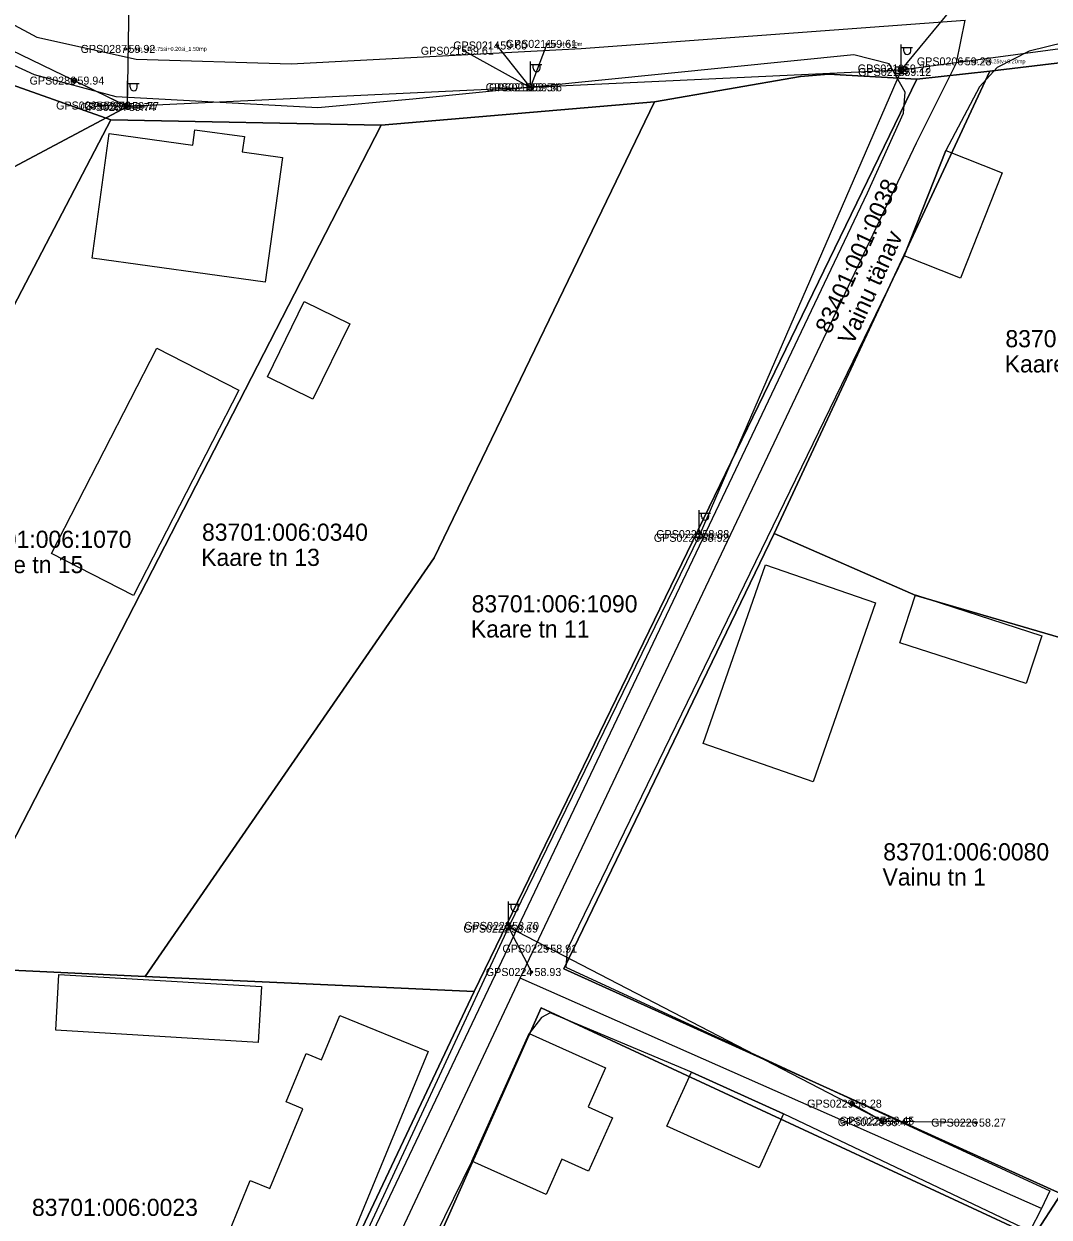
# Model space of a CAD drawing. Extents: x 580119 to 583377, y 6518915 to 6520820.
# Drawn here: x 581623.1 to 581712.7, y 6519628.5 to 6519732.9 of the extents above; entities that cross this region are included whole.
import ezdxf

# ---------------------------------------------------------------- set-up
doc = ezdxf.new("R2010")
doc.units = 0
for name, color, linetype in [('Hoone Elu- või ühiskondlik hoone', 7, 'Continuous'), ('Hoone Kõrval- või tootmishoone', 7, 'Continuous'), ('L_AADRESS', 7, 'Continuous'), ('MAAMUDEL', 7, 'Continuous'), ('MOOTKORG-EH2000', 7, 'Continuous'), ('MOOTMPUNKT', 7, 'Continuous'), ('MOOTNR', 7, 'Continuous'), ('MPOHULIIN', 7, 'Continuous'), ('PIIR', 7, 'Continuous'), ('POST', 7, 'Continuous'), ('Rippe kõrgus', 7, 'Continuous'), ('SIOHULIIN', 7, 'Continuous'), ('SIRAJATIS', 7, 'Continuous'), ('Tee Liiklusala', 7, 'Continuous'), ('Tee Tänav Pinnas', 7, 'Continuous'), ('Tee Tänav Püsikate', 7, 'Continuous'), ('TUNNUS', 7, 'Continuous')]:
    doc.layers.add(name, color=color, linetype=linetype)

msp = doc.modelspace()

# ---------------------------------------------------------------- linework, layer by layer
at = {"layer": 'Hoone Elu- või ühiskondlik hoone'}
for points in [[(581629.07, 6519712.38), (581630.57, 6519723.28), (581637.86, 6519722.27), (581638.05, 6519723.6), (581642.37, 6519723.01), (581642.19, 6519721.68), (581645.7, 6519721.2), (581644.2, 6519710.29)], [(581697.53, 6519682.25), (581692.1, 6519666.59), (581682.48, 6519669.93), (581687.92, 6519685.58)], [(581658.44, 6519643), (581648.72, 6519619.39), (581641.45, 6519622.37), (581643.12, 6519626.43), (581641.06, 6519627.29), (581642.88, 6519631.72), (581644.61, 6519631.02), (581647.48, 6519638), (581646.03, 6519638.6), (581647.78, 6519642.84), (581649.12, 6519642.29), (581650.72, 6519646.17)], [(581674.54, 6519637.2), (581672.46, 6519632.55), (581670.13, 6519633.6), (581668.74, 6519630.5), (581662.25, 6519633.41), (581667.25, 6519644.57), (581673.94, 6519641.58), (581672.41, 6519638.16)]]:
    msp.add_lwpolyline(points, close=True, dxfattribs=at)
at = {"layer": 'Hoone Kõrval- või tootmishoone'}
for points in [[(581700.04, 6519712.59), (581703.68, 6519721.79), (581708.61, 6519719.84), (581704.97, 6519710.64)], [(581644.4, 6519702), (581647.61, 6519708.59), (581651.59, 6519706.65), (581648.37, 6519700.06)], [(581625.51, 6519686.56), (581634.71, 6519704.51), (581641.88, 6519700.84), (581632.67, 6519682.88)], [(581712.06, 6519679.37), (581710.7, 6519675.18), (581699.67, 6519678.75), (581701.03, 6519682.95)], [(581643.87, 6519648.68), (581643.58, 6519643.81), (581625.88, 6519644.86), (581626.16, 6519649.75)], [(581689.5, 6519637.55), (581687.36, 6519632.83), (581679.31, 6519636.47), (581681.44, 6519641.2)]]:
    msp.add_lwpolyline(points, close=True, dxfattribs=at)
at = {"layer": 'MOOTMPUNKT'}
for centre in [(581631.98, 6519730.68), (581661.57, 6519730.52), (581664.48, 6519730.98), (581668.85, 6519731.12), (581705.07, 6519729.59), (581699.76, 6519728.97), (581699.8, 6519728.66), (581627.52, 6519727.91), (581667.24, 6519727.33), (581667.53, 6519727.32), (581629.84, 6519725.73), (581632.02, 6519725.6), (581632.31, 6519725.69), (581682.08, 6519687.93), (581682.15, 6519688.25), (581665.43, 6519653.76), (581665.52, 6519653.99), (581668.85, 6519652), (581667.47, 6519649.96), (581695.48, 6519638.45), (581698.16, 6519636.83), (581698.32, 6519636.96), (581706.32, 6519636.79)]:
    msp.add_circle(centre, 0.1, dxfattribs=at)
at = {"layer": 'MPOHULIIN'}
for p, q in [((581667.38, 6519727.32), (581668.85, 6519731.12)), ((581632.17, 6519725.65), (581629.84, 6519725.73)), ((581665.47, 6519653.88), (581667.47, 6519649.96))]:
    msp.add_line(p, q, dxfattribs=at)
for points in [[(581735.41, 6519733.61), (581699.78, 6519728.81), (581667.38, 6519727.32), (581632.17, 6519725.65), (581588.51, 6519746.8), (581548.1, 6519772.1), (581506.27, 6519795.87), (581500.22, 6519788.21)], [(581699.78, 6519728.81), (581708.5, 6519739.39), (581711.66, 6519739.66)], [(581699.78, 6519728.81), (581682.12, 6519688.09), (581665.47, 6519653.88), (581651.78, 6519624.49)], [(581632.17, 6519725.65), (581597.69, 6519707.32), (581584.75, 6519682.99), (581566.56, 6519648.72), (581550.4, 6519618.5), (581533.47, 6519586.34), (581516.09, 6519553.13), (581497.65, 6519517.94), (581481.23, 6519486.69), (581467.73, 6519460.68), (581429.35, 6519419.09), (581418, 6519374.32)], [(581706.32, 6519636.79), (581698.24, 6519636.9), (581665.47, 6519653.88)]]:
    msp.add_lwpolyline(points, dxfattribs=at)
at = {"layer": 'PIIR'}
for points in [[(581739.49, 6519732.55), (581707.53, 6519728.73), (581701.15, 6519728.05), (581693.43, 6519728.46), (581690.97, 6519728.27), (581678.23, 6519726.06), (581654.32, 6519724.01), (581630.7, 6519724.48), (581611.94, 6519731.13), (581605.95, 6519734.79), (581570.73, 6519755.43), (581571.67, 6519757.17), (581537.79, 6519776.58), (581472.84, 6519812.4), (581454.3, 6519820.58), (581425.45, 6519836.48)], [(581642.61, 6519606.31), (581662.45, 6519648.25), (581701.15, 6519728.05), (581707.53, 6519728.73), (581688.69, 6519688.3), (581670.29, 6519650.23), (581713.76, 6519630.56), (581711.33, 6519626.84), (581668.3, 6519646.83), (581659, 6519625.86)]]:
    msp.add_lwpolyline(points, dxfattribs=at)
for points in [[(581688.69, 6519688.3), (581707.53, 6519728.73), (581739.49, 6519732.55), (581716.34, 6519678.43), (581701.05, 6519682.87)], [(581570.76, 6519656.3), (581607.19, 6519725.15), (581611.94, 6519731.13), (581630.7, 6519724.48), (581592.07, 6519650.42)], [(581658.95, 6519686.18), (581678.23, 6519726.06), (581690.97, 6519728.27), (581693.43, 6519728.46), (581701.15, 6519728.05), (581662.45, 6519648.25), (581633.71, 6519649.56)], [(581616.49, 6519650.37), (581654.32, 6519724.01), (581678.23, 6519726.06), (581658.95, 6519686.18), (581633.71, 6519649.56)], [(581592.07, 6519650.42), (581630.7, 6519724.48), (581654.32, 6519724.01), (581616.49, 6519650.37)], [(581688.69, 6519688.3), (581701.05, 6519682.87), (581716.34, 6519678.43), (581738.8, 6519670.79), (581724.56, 6519646.71), (581713.76, 6519630.56), (581670.29, 6519650.23)], [(581616.49, 6519650.37), (581633.71, 6519649.56), (581662.45, 6519648.25), (581642.61, 6519606.31), (581598.4, 6519615.73)], [(581668.3, 6519646.83), (581711.33, 6519626.84), (581739.28, 6519615.28), (581729.24, 6519593.6), (581659, 6519625.86)], [(581713.76, 6519630.56), (581724.56, 6519646.71), (581749.03, 6519634.03), (581741.24, 6519619.07), (581739.28, 6519615.28), (581711.33, 6519626.84)]]:
    msp.add_lwpolyline(points, close=True, dxfattribs=at)
at = {"layer": 'POST'}
for p, q in [((581699.78, 6519729.06), (581699.78, 6519731.06)), ((581699.78, 6519730.81), (581700.78, 6519730.81)), ((581700.01, 6519730.49), (581700.01, 6519730.81)), ((581700.62, 6519730.49), (581700.62, 6519730.81)), ((581667.38, 6519727.57), (581667.38, 6519729.57)), ((581667.38, 6519729.32), (581668.38, 6519729.32)), ((581667.61, 6519729), (581667.61, 6519729.32)), ((581668.22, 6519729), (581668.22, 6519729.32)), ((581699.78, 6519728.81), (581699.78, 6519728.81)), ((581632.17, 6519725.9), (581632.17, 6519727.9)), ((581632.17, 6519727.65), (581633.17, 6519727.65)), ((581632.39, 6519727.33), (581632.39, 6519727.65)), ((581633.01, 6519727.33), (581633.01, 6519727.65)), ((581667.38, 6519727.32), (581667.38, 6519727.32)), ((581632.17, 6519725.65), (581632.17, 6519725.65)), ((581682.12, 6519688.34), (581682.12, 6519690.34)), ((581682.12, 6519690.09), (581683.12, 6519690.09)), ((581682.34, 6519689.77), (581682.34, 6519690.09)), ((581682.96, 6519689.77), (581682.96, 6519690.09)), ((581682.12, 6519688.09), (581682.12, 6519688.09)), ((581665.47, 6519654.13), (581665.47, 6519656.13)), ((581665.47, 6519655.88), (581666.47, 6519655.88)), ((581665.7, 6519655.55), (581665.7, 6519655.88)), ((581666.31, 6519655.55), (581666.31, 6519655.88)), ((581665.47, 6519653.88), (581665.47, 6519653.88))]:
    msp.add_line(p, q, dxfattribs=at)
for points in [[(581627.52, 6519727.91), (581632.17, 6519725.65)], [(581695.48, 6519638.45), (581698.24, 6519636.9)]]:
    msp.add_lwpolyline(points, dxfattribs=at)
for centre, radius in [((581699.78, 6519728.81), 0.25), ((581627.52, 6519727.91), 0.2), ((581667.38, 6519727.32), 0.25), ((581632.17, 6519725.65), 0.25), ((581682.12, 6519688.09), 0.25), ((581665.47, 6519653.88), 0.25), ((581695.48, 6519638.45), 0.2), ((581698.24, 6519636.9), 0.25)]:
    msp.add_circle(centre, radius, dxfattribs=at)
for centre in [(581700.31, 6519730.49), (581667.92, 6519729), (581632.7, 6519727.33), (581682.65, 6519689.77), (581666.01, 6519655.55)]:
    msp.add_arc(centre, 0.306, 180, 0, dxfattribs=at)
at = {"layer": 'SIOHULIIN'}
msp.add_line((581661.57, 6519730.52), (581667.38, 6519727.32), dxfattribs=at)
for points in [[(581632.17, 6519725.65), (581588.51, 6519746.8), (581548.1, 6519772.1), (581506.27, 6519795.87)], [(581667.38, 6519727.32), (581632.17, 6519725.65), (581632.41, 6519742.48)], [(581699.78, 6519728.81), (581667.38, 6519727.32), (581664.48, 6519730.98)], [(581429.35, 6519419.09), (581467.73, 6519460.68), (581481.23, 6519486.69), (581497.65, 6519517.94), (581516.09, 6519553.13), (581533.47, 6519586.34), (581550.4, 6519618.5), (581566.56, 6519648.72), (581584.75, 6519682.99), (581597.69, 6519707.32), (581632.17, 6519725.65)]]:
    msp.add_lwpolyline(points, dxfattribs=at)
at = {"layer": 'SIRAJATIS'}
msp.add_lwpolyline([(581699.28, 6519729.11), (581700.28, 6519729.11), (581700.28, 6519728.51), (581699.28, 6519728.51)], close=True, dxfattribs=at)
for centre, radius in [((581699.58, 6519728.81), 0.0304), ((581699.58, 6519728.81), 0.029), ((581699.58, 6519728.81), 0.0277), ((581699.58, 6519728.81), 0.0263), ((581699.58, 6519728.81), 0.0249), ((581699.58, 6519728.81), 0.0236), ((581699.58, 6519728.81), 0.0222), ((581699.58, 6519728.81), 0.0209), ((581699.58, 6519728.81), 0.0195), ((581699.58, 6519728.81), 0.0181), ((581699.58, 6519728.81), 0.0168), ((581699.58, 6519728.81), 0.0154), ((581699.58, 6519728.81), 0.014), ((581699.58, 6519728.81), 0.0127), ((581699.58, 6519728.81), 0.0113), ((581699.58, 6519728.81), 0.00996), ((581699.58, 6519728.81), 0.0086), ((581699.58, 6519728.81), 0.00724), ((581699.58, 6519728.81), 0.00587), ((581699.58, 6519728.81), 0.00451), ((581699.58, 6519728.81), 0.00315), ((581699.58, 6519728.81), 0.00179), ((581699.58, 6519728.81), 0.000426), ((581699.98, 6519728.81), 0.0304), ((581699.98, 6519728.81), 0.029), ((581699.98, 6519728.81), 0.0277), ((581699.98, 6519728.81), 0.0263), ((581699.98, 6519728.81), 0.0249), ((581699.98, 6519728.81), 0.0236), ((581699.98, 6519728.81), 0.0222), ((581699.98, 6519728.81), 0.0209), ((581699.98, 6519728.81), 0.0195), ((581699.98, 6519728.81), 0.0181), ((581699.98, 6519728.81), 0.0168), ((581699.98, 6519728.81), 0.0154), ((581699.98, 6519728.81), 0.014), ((581699.98, 6519728.81), 0.0127), ((581699.98, 6519728.81), 0.0113), ((581699.98, 6519728.81), 0.00996), ((581699.98, 6519728.81), 0.0086), ((581699.98, 6519728.81), 0.00724), ((581699.98, 6519728.81), 0.00587), ((581699.98, 6519728.81), 0.00451), ((581699.98, 6519728.81), 0.00315), ((581699.98, 6519728.81), 0.00179), ((581699.98, 6519728.81), 0.000426)]:
    msp.add_circle(centre, radius, dxfattribs=at)
at = {"layer": 'Tee Liiklusala'}
for points in [[(581644.12, 6519607.31), (581696.84, 6519718.1), (581699.98, 6519725.05), (581700.13, 6519726.91), (581698.74, 6519729.38), (581695.65, 6519730.16), (581657.1, 6519726.3), (581648.78, 6519725.52), (581631.18, 6519726.49), (581624.02, 6519728.42), (581614.73, 6519732.68), (581612.22, 6519732.35), (581611.06, 6519731.74), (581610.38, 6519731.19), (581607.3, 6519727.42), (581603.95, 6519720.81), (581598.73, 6519711.42), (581573.57, 6519661.9), (581548.72, 6519617.24)], [(581714.06, 6519731.24), (581710.97, 6519730.47), (581708.18, 6519729.07), (581706.63, 6519727.37), (581703.68, 6519721.79), (581700.04, 6519712.59), (581670.59, 6519651.92), (581670.46, 6519650.39), (581712.76, 6519630.82), (581712.05, 6519629.28), (581711.01, 6519627.31), (581689.5, 6519637.55), (581681.44, 6519641.2), (581669.09, 6519646.38), (581668.33, 6519645.97), (581667.25, 6519644.57), (581662.25, 6519633.41), (581639.04, 6519586.12)]]:
    msp.add_lwpolyline(points, dxfattribs=at)
at = {"layer": 'Tee Tänav Pinnas'}
msp.add_lwpolyline([(581712.05, 6519629.28), (581666.47, 6519649.43)], dxfattribs=at)
at = {"layer": 'Tee Tänav Püsikate'}
for points in [[(581611.37, 6519738.64), (581624.23, 6519731.7), (581632.92, 6519729.78), (581646.46, 6519729.39), (581671.81, 6519730.71), (581705.38, 6519733.2)], [(581666.47, 6519649.43), (581701.13, 6519722.48), (581704.62, 6519729.45), (581705.38, 6519733.2)], [(581571.4, 6519448.2), (581588.72, 6519485.71), (581629.79, 6519571.37), (581666.47, 6519649.43)]]:
    msp.add_lwpolyline(points, dxfattribs=at)

# ---------------------------------------------------------------- texts
at = {"layer": 'L_AADRESS'}
msp.add_text('Vainu tänav', height=1.5, rotation=65.4378, dxfattribs=at).set_placement((581695.55, 6519704.7))
for s, p in [('Kaare tn 9', (581708.83, 6519702.39)), ('Kaare tn 13', (581638.6, 6519685.47)), ('Kaare tn 15', (581617.93, 6519684.84)), ('Kaare tn 11', (581662.17, 6519679.21)), ('Vainu tn 1', (581698.15, 6519657.52))]:
    msp.add_text(s, height=1.5, dxfattribs=at).set_placement(p)
at = {"layer": 'MAAMUDEL'}
for s, p in [(' mp_ohl4.90m', (581668.85, 6519730.94)), (' kaabel', (581632.02, 6519725.43)), (' kaabel', (581632.31, 6519725.52)), (' kaabel', (581682.08, 6519687.75)), (' kaabel', (581682.15, 6519688.08))]:
    msp.add_text(s, height=0.35, dxfattribs=at).set_placement(p)
at = {"layer": 'MOOTKORG-EH2000'}
for s, p in [(' 59.61', (581668.85, 6519730.77)), (' 59.92', (581631.98, 6519730.33)), (' 59.61', (581661.57, 6519730.17)), (' 59.60', (581664.48, 6519730.63)), (' 59.22', (581699.76, 6519728.62)), (' 59.28', (581705.07, 6519729.24)), (' 59.94', (581627.52, 6519727.56)), (' 59.12', (581699.8, 6519728.31)), (' 59.54', (581667.24, 6519726.98)), (' 59.56', (581667.53, 6519726.97)), (' 59.78', (581629.84, 6519725.38)), (' 59.74', (581632.02, 6519725.25)), (' 59.77', (581632.31, 6519725.34)), (' 58.88', (581682.15, 6519687.9)), (' 58.92', (581682.08, 6519687.58)), (' 58.70', (581665.52, 6519653.64)), (' 58.69', (581665.43, 6519653.41)), (' 58.91', (581668.85, 6519651.65)), (' 58.93', (581667.47, 6519649.61)), (' 58.28', (581695.48, 6519638.1)), (' 58.47', (581698.16, 6519636.48)), (' 58.45', (581698.32, 6519636.61)), (' 58.27', (581706.32, 6519636.44))]:
    msp.add_text(s, height=0.7, dxfattribs=at).set_placement(p)
at = {"layer": 'MOOTNR'}
for s, p in [('GPS0211 ', (581665.21, 6519730.77)), ('GPS0287 ', (581628.06, 6519730.33)), ('GPS0215 ', (581657.79, 6519730.17)), ('GPS0214 ', (581660.63, 6519730.63)), ('GPS0219 ', (581695.98, 6519728.62)), ('GPS0206 ', (581701.15, 6519729.24)), ('GPS0286 ', (581623.6, 6519727.56)), ('GPS0218 ', (581696.02, 6519728.31)), ('GPS0213 ', (581663.46, 6519726.98)), ('GPS0212 ', (581663.75, 6519726.97)), ('GPS0285 ', (581625.92, 6519725.38)), ('GPS0284 ', (581628.03, 6519725.25)), ('GPS0283 ', (581628.39, 6519725.34)), ('GPS0221 ', (581678.37, 6519687.9)), ('GPS0220 ', (581678.16, 6519687.58)), ('GPS0223 ', (581661.6, 6519653.64)), ('GPS0222 ', (581661.51, 6519653.41)), ('GPS0225 ', (581664.93, 6519651.65)), ('GPS0224 ', (581663.48, 6519649.61)), ('GPS0229 ', (581691.56, 6519638.1)), ('GPS0228 ', (581694.24, 6519636.48)), ('GPS0227 ', (581694.4, 6519636.61)), ('GPS0226 ', (581702.4, 6519636.44))]:
    msp.add_text(s, height=0.7, dxfattribs=at).set_placement(p)
at = {"layer": 'Rippe kõrgus'}
for s, p in [(' el_mp_ohl6.75si+0.20si_1.50mp', (581631.98, 6519730.51)), (' el_mp_ohl8.25tv+0.20mp', (581705.07, 6519729.42))]:
    msp.add_text(s, height=0.35, dxfattribs=at).set_placement(p)
at = {"layer": 'TUNNUS'}
msp.add_text('83401:001:0038', height=1.5, rotation=65.4378, dxfattribs=at).set_placement((581693.57, 6519705.67))
for s, p in [('83701:006:1060', (581708.89, 6519704.59)), ('83701:006:1070', (581618, 6519687.05)), ('83701:006:0340', (581638.67, 6519687.67)), ('83701:006:1090', (581662.23, 6519681.41)), ('83701:006:0080', (581698.21, 6519659.72)), ('83701:006:0023', (581623.81, 6519628.63))]:
    msp.add_text(s, height=1.5, dxfattribs=at).set_placement(p)

doc.saveas('drawing.dxf')
